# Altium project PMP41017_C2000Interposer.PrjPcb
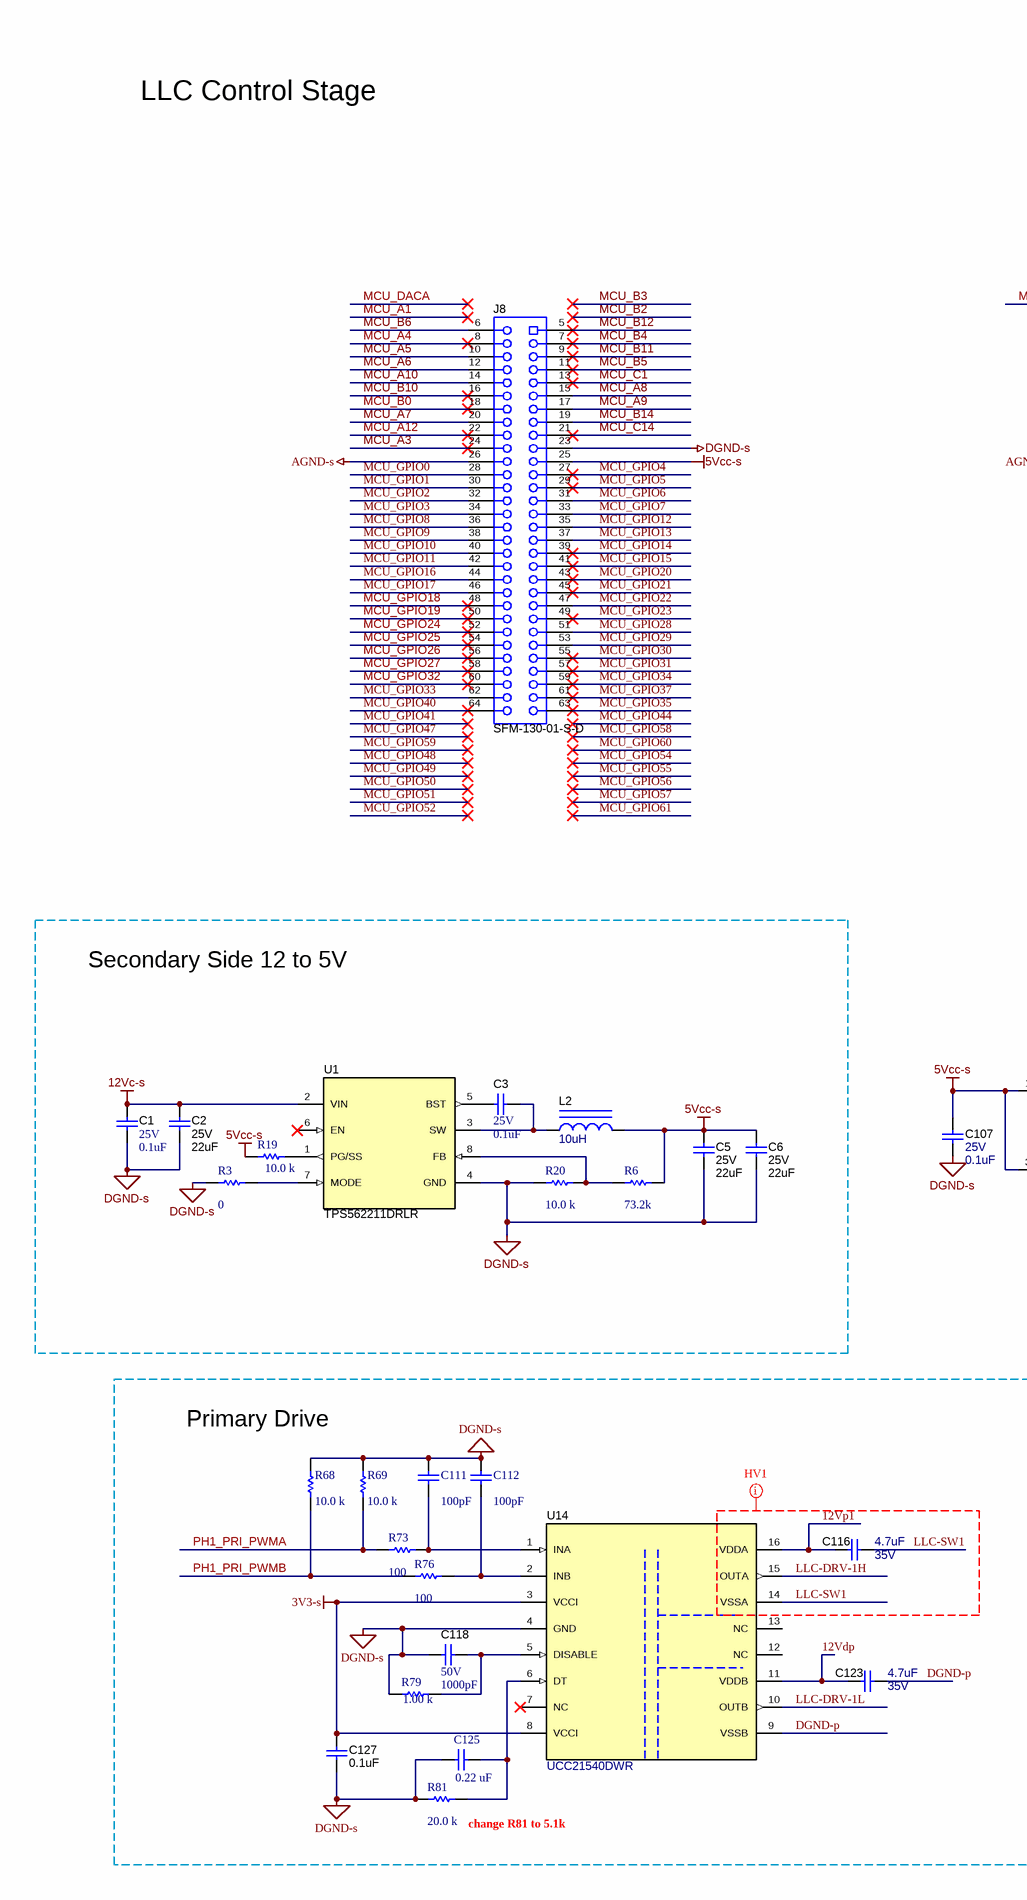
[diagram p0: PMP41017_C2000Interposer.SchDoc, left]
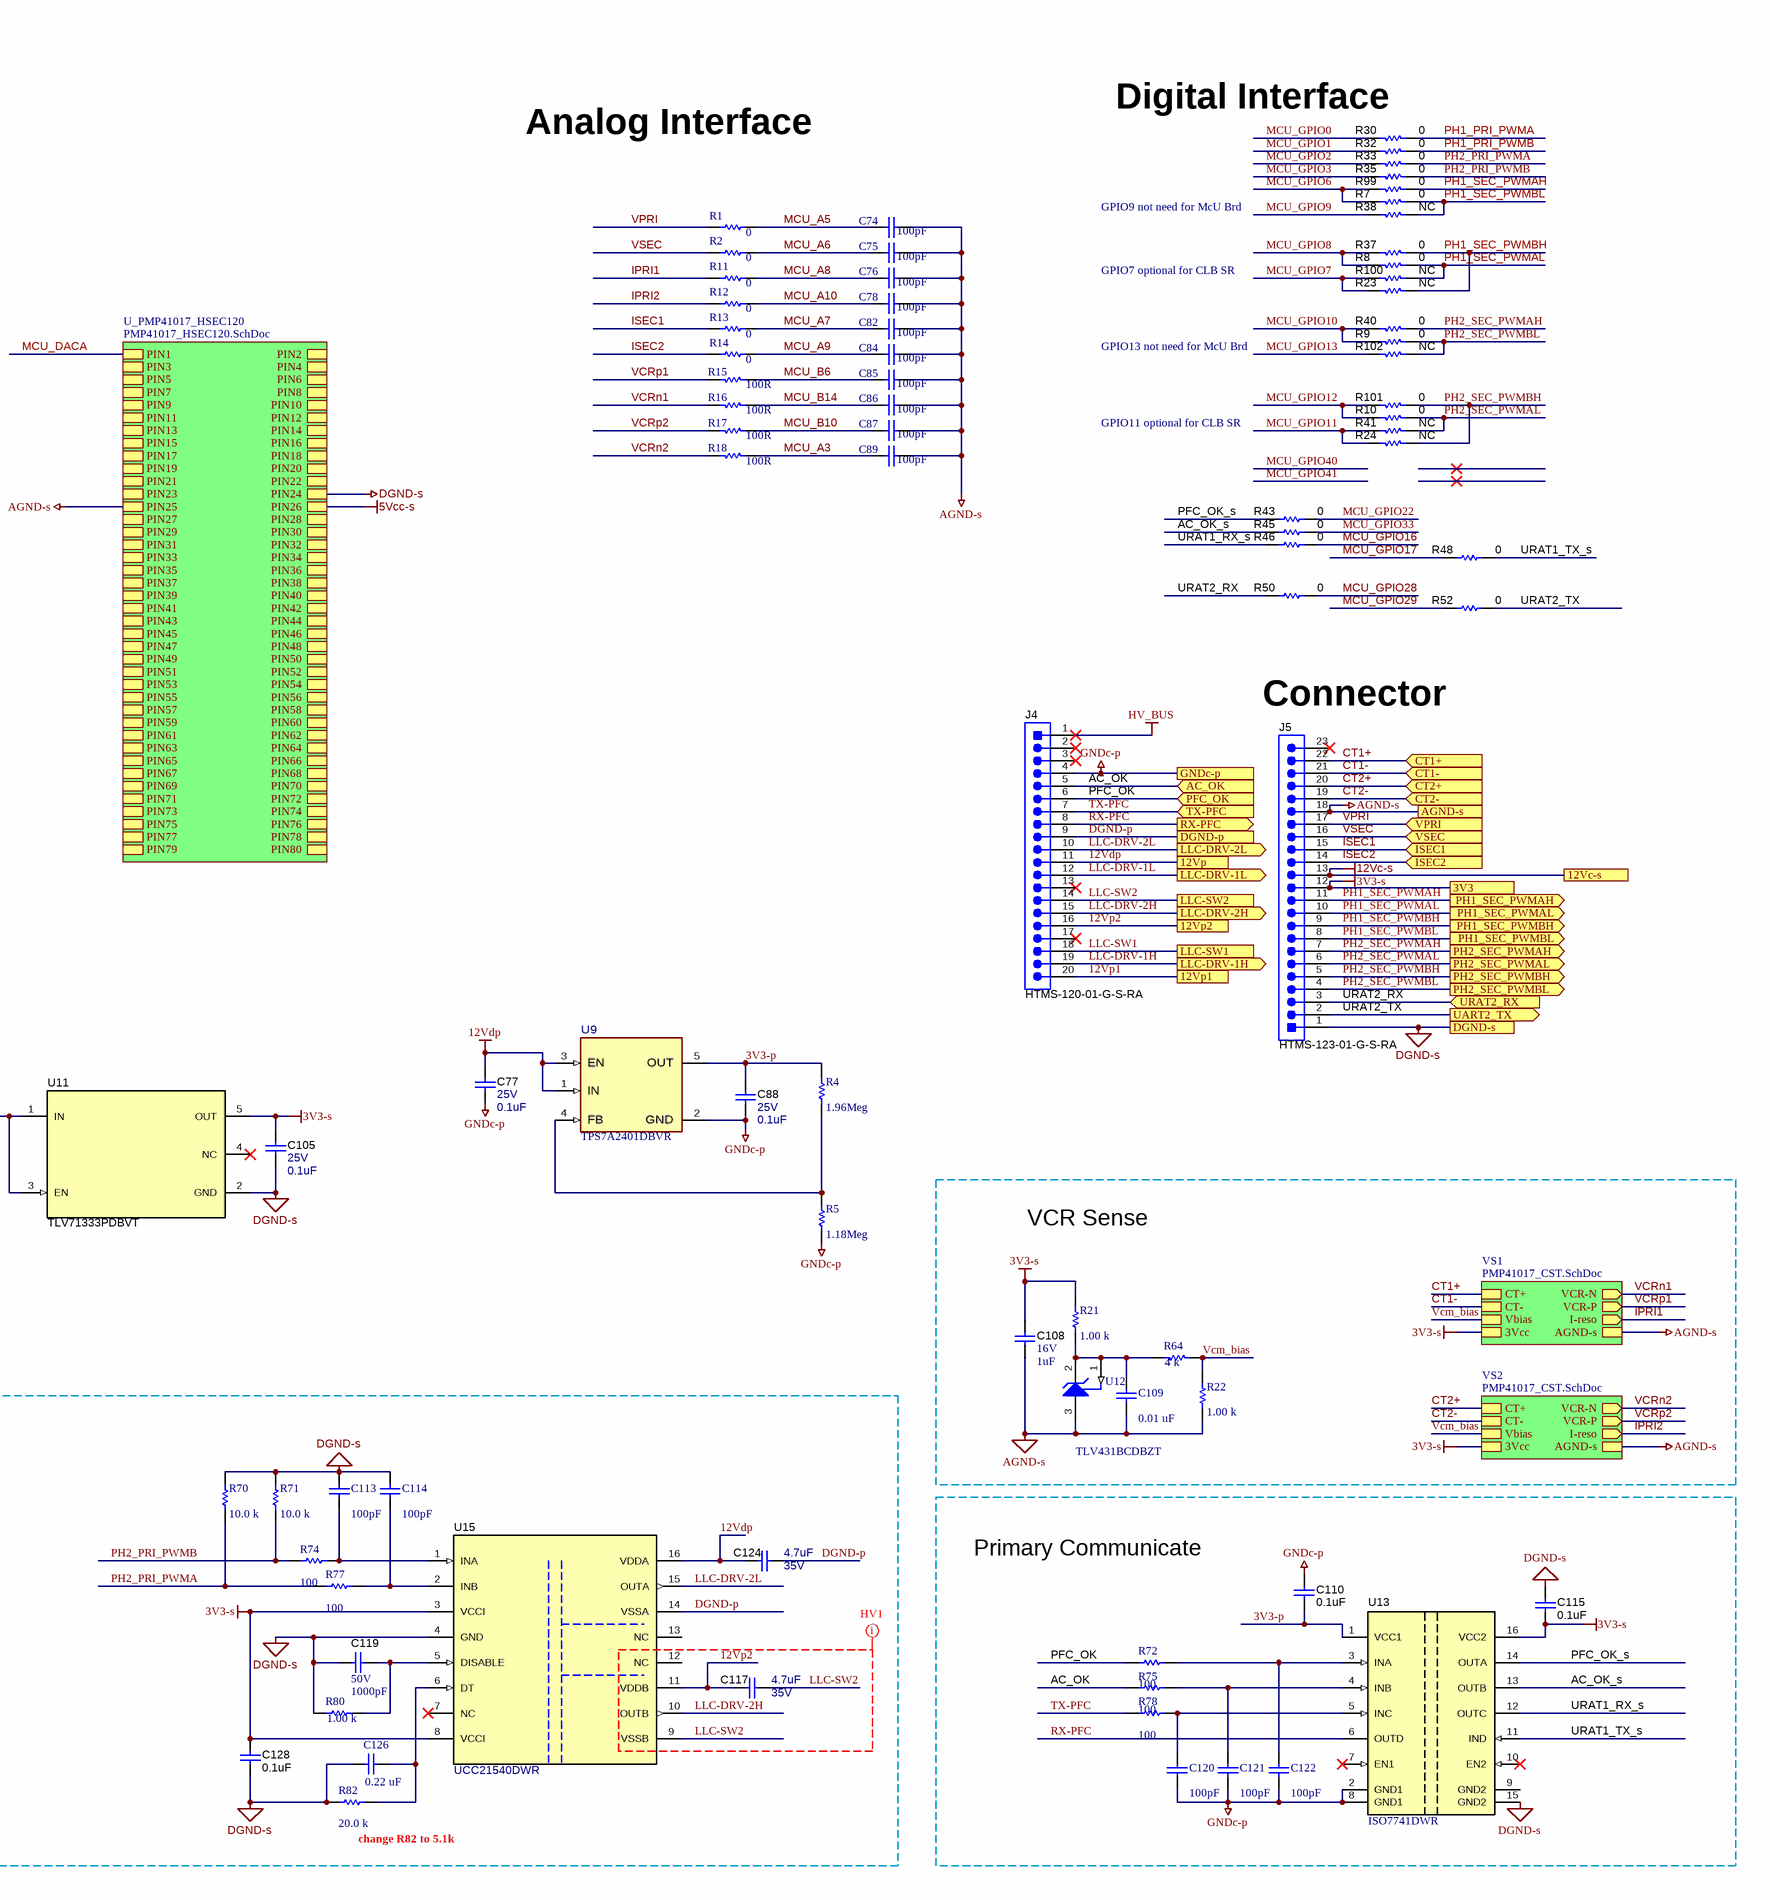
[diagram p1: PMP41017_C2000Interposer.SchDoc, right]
CopyrightYear: 2022; DrawnBy: Desheng Guo; EVM_orderable: Not Orderable; PCB_Layout: Desheng Guo; PCB_Rev: E1; PRJ_Customer: Public Release; PRJ_Engineer: Desheng Guo; PRJ_Number: PMP41017; PRJ_Title: CRPS 12V 3000W LLC C2000 Interposer; SCH_Rev: E1; TechSupport: http://www.ti.com/support; TID: PMP41017
3 sheets, 159 parts. Net scope: hierarchical (ports join the sheet entries above them; power ports are global).
Board file: PMP41017_C2000Interposer.PcbDoc
Sheets:
  PMP41017_C2000Interposer.SchDoc
    VS1 = PMP41017_CST.SchDoc
    VS2 = PMP41017_CST.SchDoc
    U_PMP41017_HSEC120 = PMP41017_HSEC120.SchDoc

## Sheet PMP41017_C2000Interposer.SchDoc: PMP41017 C2000 Interposer
size A2; Date: Not shown in title block; ApprovedBy: Not shown in title block; CheckedBy: Not shown in title block; Author: Not shown in title block; CompanyName: Not shown in title block; DrawnBy1: Desheng Guo; Engineer: Not shown in title block; Organization: Not shown in title block; Address1: Not shown in title block; Address2: Not shown in title block; Address3: Not shown in title block; Address4: Not shown in title block; DocumentNumber: 1; Revision: A; SheetNumber: 1; SheetTotal: 3; PageSetup: Record=PageOptions¦CenterHorizontal=True¦CenterVertical=True¦PrintScale=0.69¦XCorrection=1.00¦YCorrection=1.00¦PrintKind=0¦BorderSize=5000000¦LeftOffset=0¦BottomOffset=0¦Orientation=2¦PaperLength=1000¦PaperWidth=1000¦Scale=100¦PaperSource=15¦PrintQuality=600¦MediaType=1¦DitherType=10¦PaperKind=Letter¦PrintScaleMode=1

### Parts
C1  VDC_V: 25V  ValueDisplayed: 0.1uF  [0402]  (hidden comment: GRM155R71E104KE14D)
C2  VDC_V: 25V  ValueDisplayed: 22uF  [0805_HV]  (hidden comment: GRM21BR61E226ME44L)
C3  VDC_V: 25V  ValueDisplayed: 0.1uF  [0402]  (hidden comment: GRM155R71E104KE14D)
C5  VDC_V: 25V  ValueDisplayed: 22uF  [0805_HV]  (hidden comment: GRM21BR61E226ME44L)
C6  VDC_V: 25V  ValueDisplayed: 22uF  [0805_HV]  (hidden comment: GRM21BR61E226ME44L)
C74  value 100pF  [0402]  (hidden comment: Cap)
C75  value 100pF  [0402]  (hidden comment: Cap)
C76  value 100pF  [0402]  (hidden comment: Cap)
C77  VDC_V: 25V  ValueDisplayed: 0.1uF  [0603]  (hidden comment: C1608X7R1E104K080AA)
C78  value 100pF  [0402]  (hidden comment: Cap)
C82  value 100pF  [0402]  (hidden comment: Cap)
C84  value 100pF  [0402]  (hidden comment: Cap)
C85  value 100pF  [0402]  (hidden comment: Cap)
C86  value 100pF  [0402]  (hidden comment: Cap)
C87  value 100pF  [0402]  (hidden comment: Cap)
C88  VDC_V: 25V  ValueDisplayed: 0.1uF  [0603]  (hidden comment: C1608X7R1E104K080AA)
C89  value 100pF  [0402]  (hidden comment: Cap)
C105  VDC_V: 25V  ValueDisplayed: 0.1uF  [0603]  (hidden comment: C1608X7R1E104K080AA)
C107  VDC_V: 25V  ValueDisplayed: 0.1uF  [0603]  (hidden comment: C1608X7R1E104K080AA)
C108  VDC_V: 16V  ValueDisplayed: 1uF  [0603]  (hidden comment: GCM188R71C105MA64D)
C109  value 0.01 uF  [0402]
C110  ValueDisplayed: 0.1uF  [0402]  (hidden comment: 885012105010)
C111  value 100pF  [0402]  (hidden comment: Cap)
C112  value 100pF  [0402]  (hidden comment: Cap)
C113  value 100pF  [0402]  (hidden comment: Cap)
C114  value 100pF  [0402]  (hidden comment: Cap)
C115  ValueDisplayed: 0.1uF  [0402]  (hidden comment: 885012105010)
C116  VDC_V: 35V  ValueDisplayed: 4.7uF  [0805_HV]  (hidden comment: C2012X7R1V475K125AC)
C117  VDC_V: 35V  ValueDisplayed: 4.7uF  [0805_HV]  (hidden comment: C2012X7R1V475K125AC)
C118  VDC_V: 50V  ValueDisplayed: 1000pF  [0402]  (hidden comment: GRM155R71H102KA01D)
C119  VDC_V: 50V  ValueDisplayed: 1000pF  [0402]  (hidden comment: GRM155R71H102KA01D)
C120  value 100pF  [0402]  (hidden comment: Cap)
C121  value 100pF  [0402]  (hidden comment: Cap)
C122  value 100pF  [0402]  (hidden comment: Cap)
C123  VDC_V: 35V  ValueDisplayed: 4.7uF  [0805_HV]  (hidden comment: C2012X7R1V475K125AC)
C124  VDC_V: 35V  ValueDisplayed: 4.7uF  [0805_HV]  (hidden comment: C2012X7R1V475K125AC)
C125  value 0.22 uF  [0402]
C126  value 0.22 uF  [0402]
C127  ValueDisplayed: 0.1uF  [0402]  (hidden comment: 885012105010)
C128  ValueDisplayed: 0.1uF  [0402]  (hidden comment: 885012105010)
J4  HTMS-120-01-G-S-RA  [HTMS-120-01-G-S-RA]
J5  HTMS-123-01-G-S-RA  [HTMS-123-01-G-S-RA]
J8  SFM-130-01-S-D  [Samtec_SFM-130-01-x-D]
L2  ValueDisplayed: 10uH  [VLS252010HBX]  (hidden comment: 74438323100)
R1  value 0  [0402]
R2  value 0  [0402]
R3  value 0  [0402]
R4  value 1.96Meg  [0402]
R5  value 1.18Meg  [0402]
R6  73.2k  [0402]
R7  ValueDisplayed: 0  [0402]  (hidden comment: CRCW04020000Z0ED)
R8  ValueDisplayed: 0  [0402]  (hidden comment: CRCW04020000Z0ED)
R9  ValueDisplayed: 0  [0402]  (hidden comment: CRCW04020000Z0ED)
R10  ValueDisplayed: 0  [0402]  (hidden comment: CRCW04020000Z0ED)
R11  value 0  [0402]
R12  value 0  [0402]
R13  value 0  [0402]
R14  value 0  [0402]
R15  value 100R  [0402]
R16  value 100R  [0402]
R17  100R  [0402]
R18  value 100R  [0402]
R19  value 10.0 k  [0402]
R20  value 10.0 k  [0402]
R21  value 1.00 k  [0402]
R22  value 1.00 k  [0402]
R23  ValueDisplayed: NC  [0402]  (hidden comment: CRCW04020000Z0ED)  (no BOM)
R24  ValueDisplayed: NC  [0402]  (hidden comment: CRCW04020000Z0ED)  (no BOM)
R30  ValueDisplayed: 0  [0402]  (hidden comment: CRCW04020000Z0ED)
R32  ValueDisplayed: 0  [0402]  (hidden comment: CRCW04020000Z0ED)
R33  ValueDisplayed: 0  [0402]  (hidden comment: CRCW04020000Z0ED)
R35  ValueDisplayed: 0  [0402]  (hidden comment: CRCW04020000Z0ED)
R37  ValueDisplayed: 0  [0402]  (hidden comment: CRCW04020000Z0ED)
R38  ValueDisplayed: NC  [0402]  (hidden comment: CRCW04020000Z0ED)  (no BOM)
R40  ValueDisplayed: 0  [0402]  (hidden comment: CRCW04020000Z0ED)
R41  ValueDisplayed: NC  [0402]  (hidden comment: CRCW04020000Z0ED)  (no BOM)
R43  ValueDisplayed: 0  [0402]  (hidden comment: CRCW04020000Z0ED)
R45  ValueDisplayed: 0  [0402]  (hidden comment: CRCW04020000Z0ED)
R46  ValueDisplayed: 0  [0402]  (hidden comment: CRCW04020000Z0ED)
R48  ValueDisplayed: 0  [0402]  (hidden comment: CRCW04020000Z0ED)
R50  ValueDisplayed: 0  [0402]  (hidden comment: CRCW04020000Z0ED)
R52  ValueDisplayed: 0  [0402]  (hidden comment: CRCW04020000Z0ED)
R64  value 4 k  [0402]
R68  value 10.0 k  [0402]
R69  value 10.0 k  [0402]
R70  value 10.0 k  [0402]
R71  value 10.0 k  [0402]
R72  value 100  [0402]
R73  value 100  [0402]
R74  value 100  [0402]
R75  value 100  [0402]
R76  value 100  [0402]
R77  value 100  [0402]
R78  value 100  [0402]
R79  value 1.00 k  [0402]
R80  value 1.00 k  [0402]
R81  value 20.0 k  [0402]
R82  value 20.0 k  [0402]
R99  ValueDisplayed: 0  [0402]  (hidden comment: CRCW04020000Z0ED)
R100  ValueDisplayed: NC  [0402]  (hidden comment: CRCW04020000Z0ED)  (no BOM)
R101  ValueDisplayed: 0  [0402]  (hidden comment: CRCW04020000Z0ED)
R102  ValueDisplayed: NC  [0402]  (hidden comment: CRCW04020000Z0ED)  (no BOM)
U1  TPS562211DRLR  [DRL0008A]
U9  TPS7A2401DBVR  [DBV0005A-MFG]
U11  TLV71333PDBVT  [DBV0005A_N]
U12  TLV431BCDBZT  [DBZ0003A_N]
U13  ISO7741DWR  [DW0016B_HV]
U14  UCC21540DWR  [DW0016B_HV]
U15  UCC21540DWR  [DW0016B_HV]

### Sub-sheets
U_PMP41017_HSEC120 = PMP41017_HSEC120.SchDoc: PIN1, PIN3, PIN5, PIN7, PIN9, PIN11, PIN13, PIN15, PIN17, PIN19, PIN21, PIN23, PIN25, PIN27, PIN29, PIN31, PIN33, PIN35, PIN37, PIN39, PIN41, PIN43, PIN45, PIN47, PIN49, PIN51, PIN53, PIN55, PIN57, PIN59, PIN61, PIN63, PIN65, PIN67, PIN69, PIN71, PIN73, PIN75, PIN77, PIN79, PIN2, PIN4, PIN6, PIN8, PIN10, PIN12, PIN14, PIN16, PIN18, PIN20, PIN22, PIN24, PIN26, PIN28, PIN30, PIN32, PIN34, PIN36, PIN38, PIN40, PIN42, PIN44, PIN46, PIN48, PIN50, PIN52, PIN54, PIN56, PIN58, PIN60, PIN62, PIN64, PIN66, PIN68, PIN70, PIN72, PIN74, PIN76, PIN78, PIN80
VS1 = PMP41017_CST.SchDoc: CT+, CT-, Vbias, AGND-s, VCR-N (out), VCR-P (out), I-reso (out), 3Vcc
VS2 = PMP41017_CST.SchDoc: CT+, CT-, Vbias, AGND-s, VCR-N (out), VCR-P (out), I-reso (out), 3Vcc

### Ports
3V3, 12Vc-s, 12Vp, 12Vp1, 12Vp2, AC_OK (in), AGND-s, CT1+ (in), CT1- (in), CT2+ (in), CT2- (in), DGND-p, DGND-s, GNDc-p, ISEC1 (in), ISEC2 (in), LLC-DRV-1H (out), LLC-DRV-1L (out), LLC-DRV-2H (out), LLC-DRV-2L (out), LLC-SW1, LLC-SW2, PFC_OK (in), PH1_SEC_PWMAH (out), PH1_SEC_PWMAL (out), PH1_SEC_PWMBH (out), PH1_SEC_PWMBL (out), PH2_SEC_PWMAH (out), PH2_SEC_PWMAL (out), PH2_SEC_PWMBH (out), PH2_SEC_PWMBL (out), RX-PFC (out), TX-PFC (in), UART2_TX (out), URAT2_RX (in), VPRI (in), VSEC (in)

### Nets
3V3-s: C105.1 C108.1 C115.1 C127.1 C128.1 J5.12 R21.2 U11.5(OUT) U13.16(VCC2) U14.3(VCCI) U14.8(VCCI) U15.3(VCCI) U15.8(VCCI) ; port 3V3, sheet VS1/3Vcc, sheet VS2/3Vcc
5Vcc-s: C5.1 C6.1 C107.1 J8.25 L2.2 R6.2 R19.2 U11.1(IN) U11.3(EN) ; sheet U_PMP41017_HSEC120/PIN26
12Vc-s: C1.2 C2.1 J5.13 U1.2(VIN) ; port 12Vc-s
12Vdp: C77.1 C123.1 C124.1 J4.11 U9.1(IN) U9.3(EN) U14.11(VDDB) U15.16(VDDA) ; port 12Vp
AGND-s: C74.1 C75.1 C76.1 C78.1 C82.1 C84.1 C85.1 C86.1 C87.1 C89.1 C108.2 C109.1 J5.18 J8.26 R22.1 U12.3(ANODE) ; port AGND-s, sheet VS1/AGND-s, sheet VS2/AGND-s, sheet U_PMP41017_HSEC120/PIN25
CT1+: J5.20 J5.22 ; port CT1+, port CT2+, sheet VS1/CT+, sheet VS2/CT+  [also labelled CT2+]
CT1-: J5.19 J5.21 ; port CT1-, port CT2-, sheet VS1/CT-, sheet VS2/CT-  [also labelled CT2-]
DGND-s: C1.1 C2.2 C5.2 C6.2 C105.2 C107.2 C111.2 C112.2 C113.2 C114.2 C115.2 C118.2 C119.2 C125.1 C126.1 C127.2 C128.2 J5.1 J8.23 R3.1 R20.2 R68.2 R69.2 R70.2 R71.2 R79.1 R80.1 R81.1 R82.1 U1.4(GND) U11.2(GND) U13.15(GND2) U14.4(GND) U15.4(GND) ; port DGND-s, sheet U_PMP41017_HSEC120/PIN24
GNDc-p: C77.2 C88.2 C110.2 C120.1 C121.1 C122.1 J4.4 R5.1 U9.2(GND) U13.2(GND1) U13.8(GND1) ; port GNDc-p
HV_BUS: J4.1
Vcm_bias: R22.2 R64.2 ; sheet VS1/Vbias, sheet VS2/Vbias
3V3-p: C88.1 C110.1 R4.2 U9.5(OUT) U13.1(VCC1)  [project net 3V3-p_1]
12Vp1: C116.1 J4.20 U14.16(VDDA) ; port 12Vp1
12Vp2: C117.1 J4.16 U15.11(VDDB) ; port 12Vp2
AC_OK: J4.5 R75.1 ; port AC_OK
AC_OK_s: R45.1 U13.13(OUTB)  [project net AC_OK_s_1]
DGND-p: C123.2 C124.2 J4.9 U14.9(VSSB) U15.14(VSSA) ; port DGND-p
IPRI1: R11.2 ; sheet VS1/I-reso  [project net I-reso]
IPRI2: R12.2 ; sheet VS2/I-reso  [project net I-reso]
ISEC1: J5.15 R13.2 ; port ISEC1
ISEC2: J5.14 R14.2 ; port ISEC2
LLC-DRV-1H: J4.19 U14.15(OUTA) ; port LLC-DRV-1H
LLC-DRV-1L: J4.12 U14.10(OUTB) ; port LLC-DRV-1L
LLC-DRV-2H: J4.15 U15.10(OUTB) ; port LLC-DRV-2H
LLC-DRV-2L: J4.10 U15.15(OUTA) ; port LLC-DRV-2L
LLC-SW1: C116.2 J4.18 U14.14(VSSA) ; port LLC-SW1
LLC-SW2: C117.2 J4.14 U15.9(VSSB) ; port LLC-SW2
MCU_A3: C89.2 J8.24 R18.1  [project net MCU_A3_1]
MCU_A4: J8.8  [project net MCU_A4_1]
MCU_A5: C74.2 J8.10 R1.1  [project net MCU_A5_1]
MCU_A6: C75.2 J8.12 R2.1  [project net MCU_A6_1]
MCU_A7: C82.2 J8.20 R13.1  [project net MCU_A7_1]
MCU_A8: C76.2 J8.15 R11.1  [project net MCU_A8_1]
MCU_A9: C84.2 J8.17 R14.1  [project net MCU_A9_1]
MCU_A10: C78.2 J8.14 R12.1  [project net MCU_A10_1]
MCU_A12: J8.22  [project net MCU_A12_1]
MCU_B0: J8.18  [project net MCU_B0_1]
MCU_B4: J8.7  [project net MCU_B4_1]
MCU_B5: J8.11  [project net MCU_B5_1]
MCU_B6: C85.2 J8.6 R15.1  [project net MCU_B6_1]
MCU_B10: C87.2 J8.16 R17.1  [project net MCU_B10_1]
MCU_B11: J8.9  [project net MCU_B11_1]
MCU_B12: J8.5  [project net MCU_B12_1]
MCU_B14: C86.2 J8.19 R16.1  [project net MCU_B14_1]
MCU_C1: J8.13  [project net MCU_C1_1]
MCU_C14: J8.21  [project net MCU_C14_1]
MCU_GPIO0: J8.28 R30.2  [project net MCU_GPIO0_1]
MCU_GPIO1: J8.30 R32.2  [project net MCU_GPIO1_1]
MCU_GPIO2: J8.32 R33.2  [project net MCU_GPIO2_1]
MCU_GPIO3: J8.34 R35.2  [project net MCU_GPIO3_1]
MCU_GPIO4: J8.27  [project net MCU_GPIO4_1]
MCU_GPIO5: J8.29  [project net MCU_GPIO5_1]
MCU_GPIO6: J8.31 R7.2 R99.2  [project net MCU_GPIO6_1]
MCU_GPIO7: J8.33 R23.2 R100.2  [project net MCU_GPIO7_1]
MCU_GPIO8: J8.36 R8.2 R37.2  [project net MCU_GPIO8_1]
MCU_GPIO9: J8.38 R38.2  [project net MCU_GPIO9_1]
MCU_GPIO10: J8.40 R9.2 R40.2  [project net MCU_GPIO10_1]
MCU_GPIO11: J8.42 R24.2 R41.2  [project net MCU_GPIO11_1]
MCU_GPIO12: J8.35 R10.2 R101.2  [project net MCU_GPIO12_1]
MCU_GPIO13: J8.37 R102.2  [project net MCU_GPIO13_1]
MCU_GPIO14: J8.39  [project net MCU_GPIO14_1]
MCU_GPIO15: J8.41  [project net MCU_GPIO15_1]
MCU_GPIO16: J8.44 R46.2  [project net MCU_GPIO16_1]
MCU_GPIO17: J8.46 R48.1  [project net MCU_GPIO17_1]
MCU_GPIO18: J8.48  [project net MCU_GPIO18_1]
MCU_GPIO19: J8.50  [project net MCU_GPIO19_1]
MCU_GPIO20: J8.43  [project net MCU_GPIO20_1]
MCU_GPIO21: J8.45  [project net MCU_GPIO21_1]
MCU_GPIO22: J8.47 R43.2  [project net MCU_GPIO22_1]
MCU_GPIO23: J8.49  [project net MCU_GPIO23_1]
MCU_GPIO24: J8.52  [project net MCU_GPIO24_1]
MCU_GPIO25: J8.54  [project net MCU_GPIO25_1]
MCU_GPIO26: J8.56  [project net MCU_GPIO26_1]
MCU_GPIO27: J8.58  [project net MCU_GPIO27_1]
MCU_GPIO28: J8.51 R50.2  [project net MCU_GPIO28_1]
MCU_GPIO29: J8.53 R52.1  [project net MCU_GPIO29_1]
MCU_GPIO30: J8.55  [project net MCU_GPIO30_1]
MCU_GPIO31: J8.57  [project net MCU_GPIO31_1]
MCU_GPIO32: J8.60  [project net MCU_GPIO32_1]
MCU_GPIO33: J8.62 R45.2  [project net MCU_GPIO33_1]
MCU_GPIO34: J8.59  [project net MCU_GPIO34_1]
MCU_GPIO35: J8.63  [project net MCU_GPIO35_1]
MCU_GPIO37: J8.61  [project net MCU_GPIO37_1]
MCU_GPIO40: J8.64  [project net MCU_GPIO40_1]
PFC_OK: J4.6 R72.1 ; port PFC_OK
PFC_OK_s: R43.1 U13.14(OUTA)  [project net PFC_OK_s_1]
PH1_PRI_PWMA: R30.1 R69.1 R73.1  [project net PH1_PRI_PWMA_1]
PH1_PRI_PWMB: R32.1 R68.1 R76.1  [project net PH1_PRI_PWMB_1]
PH1_SEC_PWMAH: J5.11 R99.1 ; port PH1_SEC_PWMAH
PH1_SEC_PWMAL: J5.10 R8.1 R100.1 ; port PH1_SEC_PWMAL
PH1_SEC_PWMBH: J5.9 R23.1 R37.1 ; port PH1_SEC_PWMBH
PH1_SEC_PWMBL: J5.8 R7.1 R38.1 ; port PH1_SEC_PWMBL
PH2_PRI_PWMA: R33.1 R70.1 R77.1  [project net PH2_PRI_PWMA_1]
PH2_PRI_PWMB: R35.1 R71.1 R74.1  [project net PH2_PRI_PWMB_1]
PH2_SEC_PWMAH: J5.7 R40.1 ; port PH2_SEC_PWMAH
PH2_SEC_PWMAL: J5.6 R10.1 R41.1 ; port PH2_SEC_PWMAL
PH2_SEC_PWMBH: J5.5 R24.1 R101.1 ; port PH2_SEC_PWMBH
PH2_SEC_PWMBL: J5.4 R9.1 R102.1 ; port PH2_SEC_PWMBL
RX-PFC: J4.8 U13.6(OUTD) ; port RX-PFC
TX-PFC: J4.7 R78.1 ; port TX-PFC
URAT1_RX_s: R46.1 U13.12(OUTC)  [project net URAT1_RX_s_1]
URAT1_TX_s: R48.2 U13.11(IND)  [project net URAT1_TX_s_1]
URAT2_RX: J5.3 R50.1 ; port URAT2_RX
URAT2_TX: J5.2 R52.2 ; port UART2_TX
VCRn1: R16.2 ; sheet VS1/VCR-N  [project net VCR-N]
VCRn2: R18.2 ; sheet VS2/VCR-N  [project net VCR-N]
VCRp1: R15.2 ; sheet VS1/VCR-P  [project net VCR-P]
VCRp2: R17.2 ; sheet VS2/VCR-P  [project net VCR-P]
VPRI: J5.17 R1.2 ; port VPRI
VSEC: J5.16 R2.2 ; port VSEC
NetC3_1: C3.1 U1.5(BST)
NetC3_2: C3.2 L2.1 U1.3(SW)
NetC109_2: C109.2 R21.1 R64.1 U12.1(REF) U12.2(CATHODE)
NetC111_1: C111.1 R73.2 U14.1(INA)
NetC112_1: C112.1 R76.2 U14.2(INB)
NetC113_1: C113.1 R74.2 U15.1(INA)
NetC114_1: C114.1 R77.2 U15.2(INB)
NetC118_1: C118.1 R79.2 U14.5(DISABLE)
NetC119_1: C119.1 R80.2 U15.5(DISABLE)
NetC120_2: C120.2 R78.2 U13.5(INC)
NetC121_2: C121.2 R75.2 U13.4(INB)
NetC122_2: C122.2 R72.2 U13.3(INA)
NetC125_2: C125.2 R81.2 U14.6(DT)
NetC126_2: C126.2 R82.2 U15.6(DT)
NetR3_2: R3.2 U1.7(MODE)
NetR4_1: R4.1 R5.2 U9.4(FB)
NetR6_1: R6.1 R20.1 U1.8(FB)
NetR19_1: R19.1 U1.1(PG/SS)

Not connected (* = marked no-connect by the designer): J4 2* 3* 13* 17*; J5 23*; U1 6(EN)*; U11 4(NC)*; U13 7(EN1)* 9(GND2) 10(EN2)*; U14 7(NC)* 12(NC) 13(NC); U15 7(NC)* 12(NC) 13(NC)

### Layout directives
net class HV: 12Vp1, 12Vp2, LLC-DRV-1H, LLC-DRV-2H, LLC-SW1, LLC-SW2

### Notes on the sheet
- Analog Interface
- Digital Interface
- LLC Control Stage
- GPIO9 not need for McU Brd
- GPIO7 optional for CLB SR
- GPIO13 not need for McU Brd
- GPIO11 optional for CLB SR
- (near J5) Connector
- Secondary Side 12 to 5V
- VCR Sense
- Primary Drive
- Primary Communicate
- (near R81) change R81 to 5.1k
- (near R82) change R82 to 5.1k

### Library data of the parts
C1 C3 = CMP-0006659-2: CAP, CERM, 0.1 uF, 25 V, +/- 10%, X7R, 0402; Manufacturer: MuRata; TaMin_C: -55°C; Polarized: N; SizeAreaWB_mm2: 3; Value1: Unknown; U/M: EA; Value: 0.1uF; TaMax_C: 125°C; SizeZ_mm: 0.6; SizeX_mm: 1; SizeY_mm: 0.5; Cap_F: 100nF; AEC Category: Q200
C2 C5 C6 = CMP-0008305-2: CAP, CERM, 22 uF, 25 V, +/- 20%, X5R, 0805; Manufacturer: MuRata; TaMin_C: -55°C; Polarized: N; SizeAreaWB_mm2: 6.75; Value1: Unknown; U/M: EA; Value: 22uF; TaMax_C: 85°C; SizeZ_mm: 1.45; SizeX_mm: 2; SizeY_mm: 1.25; Cap_Case: 0805; SizeArea_mm2: 2.5; Cap_F: 22µF; AEC Category: Q200
C74-C76 C78 C82 C84-C87 C89 C111-C114 C120-C122 = Cap: CAP, CERM, 100 pF, 25 V, +/- 10%, X7R,0402
C77 C88 C105 C107 = CMP-0007039-5: CAP, CERM, 0.1 uF, 25 V, +/- 10%, X7R, 0603; Manufacturer: TDK; TaMin_C: -55°C; Polarized: N; SizeAreaWB_mm2: 4.68; Value1: Unknown; U/M: EA; Value: 0.1uF; TaMax_C: 125°C; SizeZ_mm: 1; SizeX_mm: 1.6; SizeY_mm: 0.8; SizeArea_mm2: 1.28; Cap_F: 100nF; AEC Category: Q200
C108 = CMP-0007137-5: CAP, CERM, 1 uF, 16 V, +/- 20%, X7R, AEC-Q200 Grade 1, 0603; Manufacturer: MuRata; TaMin_C: -55°C; Polarized: N; SizeAreaWB_mm2: 4.68; Value1: Unknown; U/M: EA; Value: 1uF; TaMax_C: 125°C; SizeZ_mm: 1; SizeX_mm: 1.6; SizeY_mm: 0.8; SizeArea_mm2: 1.28; CompType: Capacitor; AEC Qualified: Y; Cap_F: 1µF; AEC Category: Q200
C109 = Cap: CAP, CERM, 0.01 uF, 50 V, +/- 10%, X7R, 0402
C110 C115 = CMP-0006221-2: CAP, CERM, 0.1 uF, 10 V, +/- 20%, X5R, 0402; Manufacturer: Wurth Elektronik; Polarized: N; CompType: Capacitor; Value: 0.1uF; U/M: EA; Cap_F: 100nF; Value1: Unknown; VDC_V: 10V; TaMin_C: -55°C; TaMax_C: 85°C; SizeArea_mm2: 0.5; SizeAreaWB_mm2: 3; SizeX_mm: 1; SizeZ_mm: 0.6; AEC Category: Q200
C116 C117 C123 C124 = CMP-0007885-2: CAP, CERM, 4.7 uF, 35 V, +/- 10%, X7R, 0805; Manufacturer: TDK; TaMin_C: -55°C; ESR_ohm: 2.346m; Polarized: N; SizeAreaWB_mm2: 6.75; Value1: 0.002346 ohm; U/M: EA; Value: 4.7uF; TaMax_C: 125°C; SizeZ_mm: 1.45; SizeX_mm: 2; SizeY_mm: 1.25; Cap_Case: 0805; SizeArea_mm2: 2.5; Cap_F: 4.7µF; IRMS_A: 4.26021A; AEC Category: Q200
C118 C119 = CMP-0006673-2: CAP, CERM, 1000 pF, 50 V, +/- 10%, X7R, 0402; Manufacturer: MuRata; TaMin_C: -55°C; Polarized: N; SizeAreaWB_mm2: 3; Value1: Unknown; U/M: EA; Value: 1000pF; TaMax_C: 125°C; SizeZ_mm: 0.6; SizeX_mm: 1; SizeY_mm: 0.5; Cap_F: 1nF; AEC Category: Q200
C125 C126 = Cap: CAP, CERM, 0.22 uF, 50 V, +/- 10%, X7R, 0402
C127 C128 = CMP-0006221-2: CAP, CERM, 0.1 uF, 10 V, +/- 20%, X5R, 0402; Manufacturer: Wurth Elektronik; Polarized: N; CompType: Capacitor; Value: 0.1uF; U/M: EA; Cap_F: 100nF; Value1: Unknown; VDC_V: 10V; TaMin_C: -55°C; TaMax_C: 85°C; AEC Category: Q200; SizeArea_mm2: 0.5; SizeAreaWB_mm2: 3; SizeX_mm: 1; SizeZ_mm: 0.6
J4 = Header_20x1: Header, 1.27mm, 20x1, Gold with Tin tail, TH, Right Angle; Manufacturer: Samtec; Pitch_mm: 1.27; Gender: Male; Row_Count: 1; Current_A: 1A; Cert_UL: Y; Shrouded: N
J5 = Header_23x1: Header, 1.27mm, 23x1, Gold with Tin tail, TH, Right Angle; Manufacturer: Samtec; Pitch_mm: 1.27; Gender: Male; Row_Count: 1; Current_A: 1A; Cert_UL: Y; Shrouded: N
J8 = Receptacle_30x2: Receptacle, 1.27mm, 30x2, Gold, TH; Manufacturer: Samtec; Pitch_mm: 1.27; Gender: Female; Cert_CSA: Y; Current_A: 3.2A; Voltage_V: 250V; CT: True; Row_Count: 2; CompType: Socket Strip; CNHeader: False
L2 = CMP-0063086-1: Inductor, Wirewound, Ferrite, 10 uH, 0.68 A, 0.46 ohm, SMD; Manufacturer: Würth Elektronik; Isat: 1.35A @ 20% inductance drop; Irms: 0.60A @ 40C rise; Green_Lifecycle: Active; SizeAreaWB_mm2: 10.5; DCR_ohm: 0.46; Green_REACh: Passed; Value1: 0.843 ohm; Value: 10uH; Imax_A: 600mA; SizeZ_mm: 1; SizeX_mm: 2.5; SizeY_mm: 2; Value2: 0.6A; SizeArea_mm2: 5; Ind_H: 10µH; AEC Qualified: N; AEC Category: Q200
R1 R2 R11-R14 = Res1: RES, 0, 5%, 0.063 W, AEC-Q200 Grade 0, 0402
R3 = Res1: RES, 0, 5%, 0.1 W, AEC-Q200 Grade 0, 0402
R4 = Res1: RES, 1.96Meg, 1%, 0.1 W, 0402
R5 = Res1: RES, 1.18Meg, 1%, 0.1 W, 0402
R6 = Res1: RES, 73.2 k, 1%, 0.1 W, AEC-Q200 Grade 0, 0402
R7-R10 R23 R24 R30 R32 R33 R35 R37 R38 R40 R41 R43 R45 R46 R48 R50 R52 R99-R102 = CMP-0026822-3: RES, 0, 5%, 0.063 W, AEC-Q200 Grade 0, 0402; Manufacturer: Vishay-Dale; CompType: Resistor; Value: 0; Value_Code: 0000; Power_W: 63mW; Value2: 0.063W; VDC_V: 50V; TempCo: 200 ppm/C; SizeArea_mm2: 0.5; SizeX_mm: 1; SizeZ_mm: 0.6; EIA_Code: E24; AEC Category: Q200; AEC Qualified: Y
R15-R18 = Res1: RES, 100R, 1%, 0402
R19 R20 R68-R71 = Res1: RES, 10.0 k, 1%, 0.1 W, 0402
R21 R22 R79 R80 = Res1: RES, 1.00 k, 1%, 0402
R64 = Res1: RES, 4 k, 1%,0402
R72-R78 = Res1: RES, 100, 1%, 0402
R81 R82 = Res1: RES, 20.0 k, 1%, 0402
U1 = CMP-0861057-2: 4.2-V to 17-V Input, 2-A Synchronous Buck Converter, DRL0008A (SOT-5X3-8); Alternate Manufacturer: Texas Instruments; AEC Category: Q200; SizeX_mm: 1.6; SizeY_mm: 2.1; CompType: IC; SizeZ_mm: 0.6; SizeAreaWB_mm2: 8.06; AEC Qualified: N; SizeArea_mm2: 3.36
U9 = CMP-0089843-1: Linear Voltage Regulator IC 1 Output 200mA SOT-23-5; Manufacturer: Texas Instruments; Output Type: AdjustableProgrammable; Accuracy Percentage: 2%; AEC Qualified: No; Max Supply Voltage: 18V; Dropout Voltage: 160mV; SizeZ_mm: 1.45mm; Output Voltage: 1.24-17.75V; Min Supply Voltage: 2.4V; TJmax_C: +125°C; Nominal Supply Current: 2uA; Number Of Outputs: 1; Standoff Height: 0mm
U11 = TLV71333PQDBVRQ1: Capacitor-Free, 150-mA, Low-Dropout Regulator with Foldback Current Limit for Portable Devices, DBV0005A; Manufacturer: Texas Instruments; SymbolCreator: Altium; SizeArea_mm2: 8.12; SizeAreaWB_mm2: 14.82; SizeX_mm: 2.8; SizeY_mm: 2.9; SizeZ_mm: 1.45; CompType: IC; U/M: EA
U12 = CMP-0033068-1: Low-Voltage Adjustable Precision Shunt Regulator, 15 mA, 0 to 70 degC, 3-pin SOT-23 (DBZ), Green (RoHS & no Sb/Br); Manufacturer: Texas Instruments; Temp Coeff(Max)(ppm/ degree C): 129; VO Adj(Max)(V): 6; VO Adj(Min)(V): 1.24; Rating: Catalog; SubFamily: Shunt Voltage Reference; Initial Accuracy @ 25/deg C(%): 0.5; Iout/Iz(Max)(mA): 15; Min Iz for Regulation(uA): 80
U13 = CMP-0076064-3: High-Speed, Low-Power, Robust EMC Quad-Channel Digital Isolator, DW0016B (SOIC-16); Manufacturer: Texas Instruments; Green_Lifecycle: Active; AEC Category: Q200; CompType: IC; Green_REACh: Passed; SizeAreaWB_mm2: 152.52; SizeX_mm: 10.4; Rating: Catalog; SizeY_mm: 10.3; AEC Qualified: N; SizeZ_mm: 2.65; SizeArea_mm2: 107.12
U14 U15 = CMP-0073643-4: 4A/6A, 5.7 kVrms Isolated Dual Channel Gate Driver, DW0016B (SOIC-16); Alternate Manufacturer: Texas Instruments; CompType: IC; SizeArea_mm2: 107.12; SizeY_mm: 10.3; Rating: Catalog; AEC Category: Q200; SizeZ_mm: 2.65; SizeX_mm: 10.4; AEC Qualified: N; SizeAreaWB_mm2: 152.52

## Sheet PMP41017_CST.SchDoc
size A3; Date: Not shown in title block; ApprovedBy: Not shown in title block; CheckedBy: Not shown in title block; Author: Not shown in title block; CompanyName: Not shown in title block; DrawnBy: Desheng Guo; Engineer: Not shown in title block; Organization: Not shown in title block; Address1: Not shown in title block; Address2: Not shown in title block; Address3: Not shown in title block; Address4: Not shown in title block; DocumentNumber: 1; Revision: Use project parameter SCH_Rev; SheetNumber: 6; SheetTotal: 7; PageSetup: Record=PageOptions¦CenterHorizontal=True¦CenterVertical=True¦PrintScale=0.69¦XCorrection=1.00¦YCorrection=1.00¦PrintKind=0¦BorderSize=5000000¦LeftOffset=0¦BottomOffset=0¦Orientation=2¦PaperLength=1000¦PaperWidth=1000¦Scale=100¦PaperSource=15¦PrintQuality=600¦MediaType=1¦DitherType=10¦PaperKind=Letter¦PrintScaleMode=1
Used 2 times, as channels VS1, VS2. Parts and nets are listed once, with the designators drawn on the sheet.
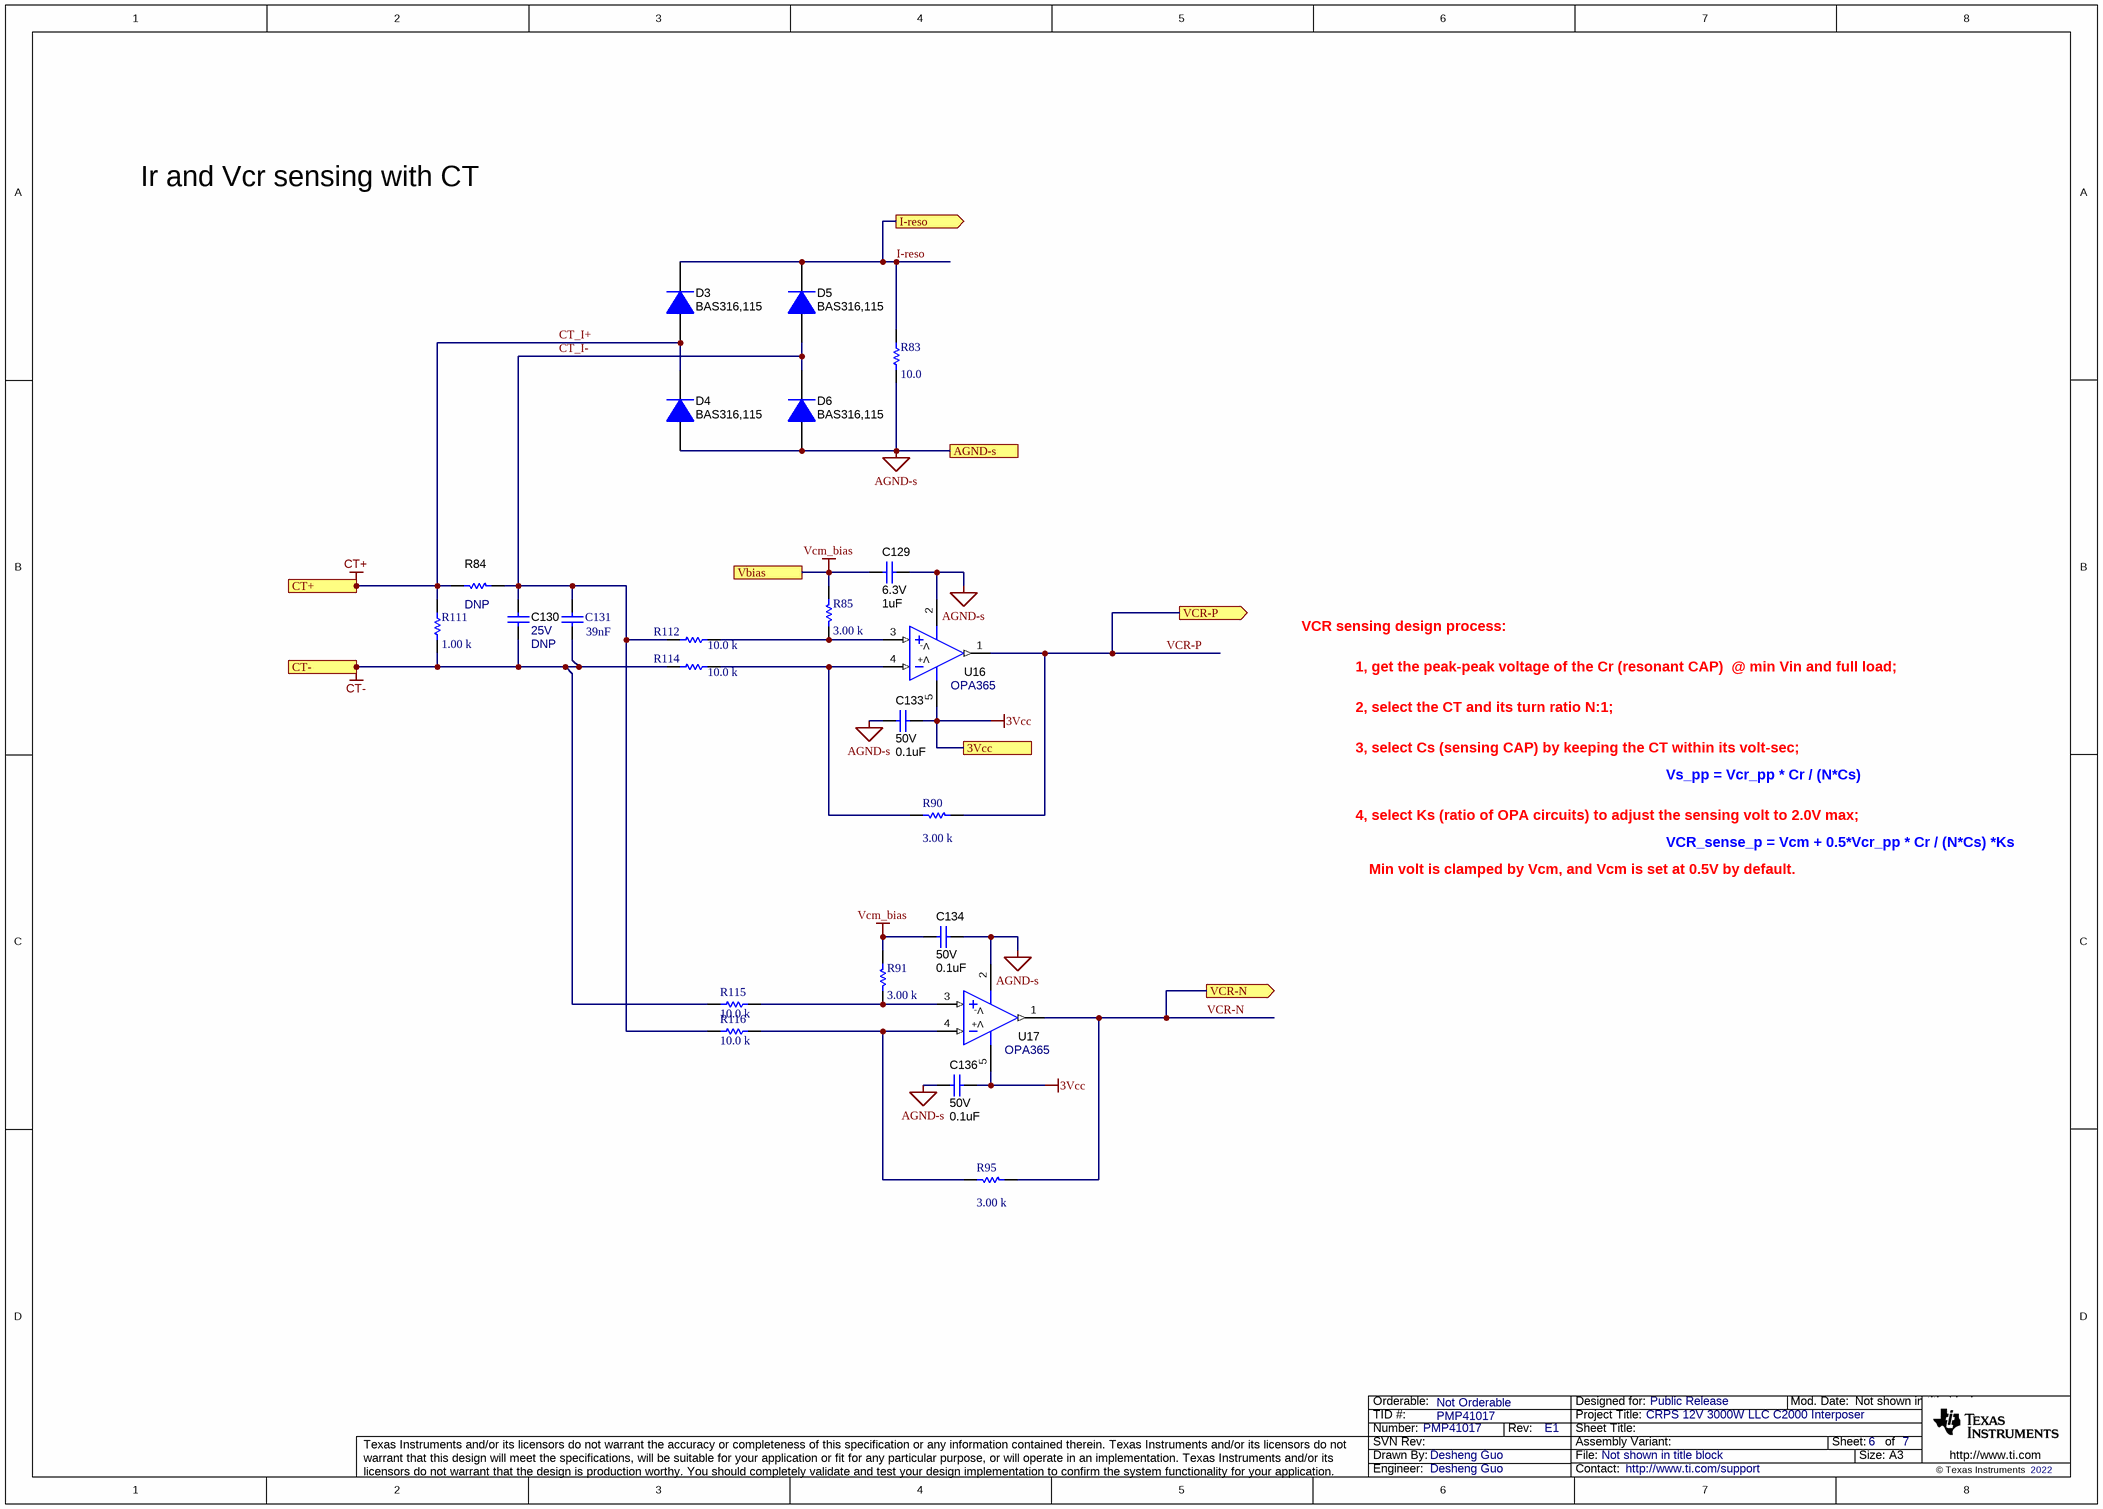
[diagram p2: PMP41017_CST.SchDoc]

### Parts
C129  VDC_V: 6.3V  ValueDisplayed: 1uF  [0402]  (hidden comment: GRM155R70J105KA12D)
C130  VDC_V: 25V  [0603]  (hidden comment: DNP)  (no BOM)
C131  value 39nF  [0402]
C133  VDC_V: 50V  ValueDisplayed: 0.1uF  [0402]  (hidden comment: C1005X7R1H104K050BE)
C134  VDC_V: 50V  ValueDisplayed: 0.1uF  [0402]  (hidden comment: C1005X7R1H104K050BE)
C136  VDC_V: 50V  ValueDisplayed: 0.1uF  [0402]  (hidden comment: C1005X7R1H104K050BE)
D3  BAS316,115  [SOD-323]
D4  BAS316,115  [SOD-323]
D5  BAS316,115  [SOD-323]
D6  BAS316,115  [SOD-323]
R83  value 10.0  [0402]
R84  ValueDisplayed: DNP  [0603]  (hidden comment: NC)  (no BOM)
R85  value 3.00 k  [0402]
R90  value 3.00 k  [0402]
R91  value 3.00 k  [0402]
R95  value 3.00 k  [0402]
R111  value 1.00 k  [0402]
R112  value 10.0 k  [0402]
R114  value 10.0 k  [0402]
R115  value 10.0 k  [0402]
R116  value 10.0 k  [0402]
U16  OPA365  [DBV0005A_N]
U17  OPA365  [DBV0005A_N]

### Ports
3Vcc, AGND-s, CT+, CT-, I-reso (out), Vbias, VCR-N (out), VCR-P (out)

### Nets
3Vcc: C133.2 C136.2 U16.5(V+) U17.5(V+) ; port 3Vcc
AGND-s: C129.1 C133.1 C134.2 C136.1 D4.2(A) D6.2(A) R83.1 U16.2(V-) U17.2(V-) ; port AGND-s
CT-: C130.1 C131.2 R111.1 R114.2 R115.2 ; port CT-
CT_I+: D3.2(A) D4.1(K) R84.2 R111.2 ; port CT+  [also labelled CT+]
Vcm_bias: C129.2 C134.1 R85.1 R91.1 ; port Vbias
CT_I-: C130.2 C131.1 D5.2(A) D6.1(K) R84.1 R112.2 R116.2  [project net CT_I-_6]
I-reso: D3.1(K) D5.1(K) R83.2 ; port I-reso
VCR-N: R95.1 U17.1(OUT) ; port VCR-N
VCR-P: R90.1 U16.1(OUT) ; port VCR-P
NetR85_2: R85.2 R112.1 U16.3(IN+)
NetR90_2: R90.2 R114.1 U16.4(IN-)
NetR91_2: R91.2 R115.1 U17.3(IN+)
NetR95_2: R95.2 R116.1 U17.4(IN-)

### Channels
VS1: designators end in _VS1; ports 3Vcc=3V3-s AGND-s=AGND-s CT+=CT1+ CT-=CT1- I-reso=I-reso Vbias=Vcm_bias VCR-N=VCR-N VCR-P=VCR-P
VS2: designators end in _VS2; ports 3Vcc=3V3-s AGND-s=AGND-s CT+=CT1+ CT-=CT1- I-reso=I-reso Vbias=Vcm_bias VCR-N=VCR-N VCR-P=VCR-P

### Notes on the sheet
- Ir and Vcr sensing with CT
- VCR sensing design process:
- 1, get the peak-peak voltage of the Cr (resonant CAP)  @ min Vin and full load;
- 2, select the CT and its turn ratio N:1;
- 3, select Cs (sensing CAP) by keeping the CT within its volt-sec;
- Vs_pp = Vcr_pp * Cr / (N*Cs)
- 4, select Ks (ratio of OPA circuits) to adjust the sensing volt to 2.0V max;
- VCR_sense_p = Vcm + 0.5*Vcr_pp * Cr / (N*Cs) *Ks
- Min volt is clamped by Vcm, and Vcm is set at 0.5V by default.

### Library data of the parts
C129 = CMP-0064947-2: CAP, CERM, 1 uF, 6.3 V,+/- 10%, X7R, 0402; Manufacturer: MuRata; TaMin_C: -55°C; Polarized: N; SizeAreaWB_mm2: 3; Value1: Unknown; U/M: EA; Value: 1uF; TaMax_C: 125°C; SizeZ_mm: 0.6; SizeX_mm: 1; SizeY_mm: 0.5; Cap_F: 1µF; AEC Category: Q200
C130 = CMP-0007039-5: CAP, CERM, 39nF, 25 V, +/- 10%, NP0, 0603; Manufacturer: TDK; PartNumber: CC0603KRX7R8BB393; TaMin_C: -55°C; Polarized: N; SizeAreaWB_mm2: 4.68; Value1: Unknown; U/M: EA; TaMax_C: 125°C; SizeZ_mm: 1; SizeX_mm: 1.6; SizeY_mm: 0.8; SizeArea_mm2: 1.28; AEC Category: Q200
C131 = Cap: CAP, CERM, 39nF, 25 V, +/- 10%, NP0, 0402
C133 C134 C136 = CMP-0064946-2: CAP, CERM, 0.1 uF, 50 V,+/- 10%, X7R, 0402; Manufacturer: TDK; TaMin_C: -55°C; Polarized: N; SizeAreaWB_mm2: 3; Value1: Unknown; U/M: EA; Value: 0.1uF; TaMax_C: 125°C; SizeZ_mm: 0.6; SizeX_mm: 1; SizeY_mm: 0.5; Cap_F: 100nF; AEC Category: Q200
D3-D6 = CMP-0029006-2: Diode, Ultrafast, 100 V, 0.25 A, SOD-323; Manufacturer: Nexperia; SizeY_mm: 1.35; Value1: 0.25A; SizeAreaWB_mm2: 8.695; SizeZ_mm: 1; Io_A: 250mA; Value2: 1.4V; SizeX_mm: 2.7; Green_REACh: Incomplete; TJmax_C: 150°C; Green_Lifecycle: Not Set; Vr_V: 100V; AEC Category: Q101; Value: 100V; SizeArea_mm2: 3.645
R83 = Res1: RES, 10.0, 1%, 0402
R84 = CMP-0022680-4: RES, 10R, 1%, 0.1 W, 0603; Manufacturer: Panasonic; Power_W: 100mW; TempCo: 100 ppm/C; Value_Code: 100; U/M: EA; Value: 10; EIA_Code: E96; Res_ohm: 1k; SizeX_mm: 1.6; SizeY_mm: 0.8; SizeZ_mm: 1; SizeArea_mm2: 1.28; VDC_V: 75V; AEC Category: Q200; Value2: 0.1W
R85 R90 R91 R95 = Res1: RES, 3.00 k, 1%, 0402
R111 = Res1: RES, 1.00 k, 1%, 0402
R112 R114-R116 = Res1: RES, 10.0 k, 1%, 0.1 W, 0402
U16 U17 = CMP-0861047-2: 50-MHz, Low-Power, Gain of 6-V/V Stable, Rail-to-Rail Output CMOS Operational Amplifier, DBV0005A (SOT-23-5); Manufacturer: Texas Instruments; AEC Category: Q200; SizeY_mm: 2.9; SizeArea_mm2: 8.12; SizeX_mm: 2.8; SizeZ_mm: 1.45; SizeAreaWB_mm2: 14.82; AEC Qualified: N; CompType: IC

## Sheet PMP41017_HSEC120.SchDoc
size A3; Date: Not shown in title block; ApprovedBy: Not shown in title block; CheckedBy: Not shown in title block; Author: Not shown in title block; CompanyName: Not shown in title block; DrawnBy: Desheng Guo; Engineer: Not shown in title block; Organization: Not shown in title block; Address1: Not shown in title block; Address2: Not shown in title block; Address3: Not shown in title block; Address4: Not shown in title block; DocumentNumber: 1; Revision: Use project parameter SCH_Rev; SheetNumber: 3; SheetTotal: 3; PageSetup: Record=PageOptions¦CenterHorizontal=True¦CenterVertical=True¦PrintScale=0.69¦XCorrection=1.00¦YCorrection=1.00¦PrintKind=0¦BorderSize=5000000¦LeftOffset=0¦BottomOffset=0¦Orientation=2¦PaperLength=1000¦PaperWidth=1000¦Scale=100¦PaperSource=15¦PrintQuality=600¦MediaType=1¦DitherType=10¦PaperKind=Letter¦PrintScaleMode=1
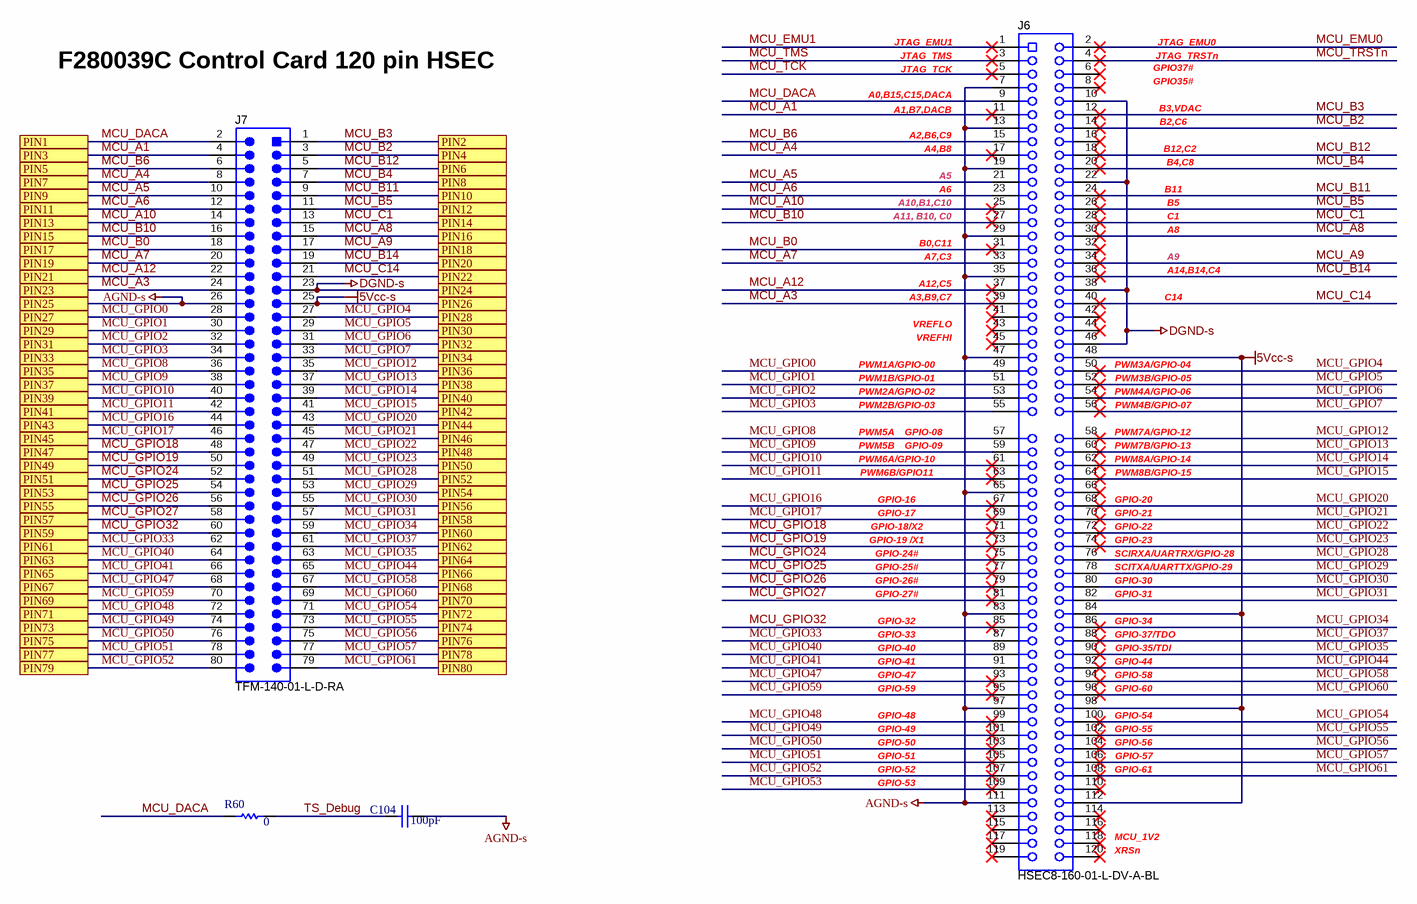
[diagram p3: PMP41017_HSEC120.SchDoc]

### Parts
C104  value 100pF  [0402]  (hidden comment: Cap)
J6  HSEC8-160-01-L-DV-A-BL  [controlCARD-120HSEC]
J7  TFM-140-01-L-D-RA  [Samtec_TFM-140-01-x-D-RA]
R60  value 0  [0402]

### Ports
PIN1, PIN2, PIN3, PIN4, PIN5, PIN6, PIN7, PIN8, PIN9, PIN10, PIN11, PIN12, PIN13, PIN14, PIN15, PIN16, PIN17, PIN18, PIN19, PIN20, PIN21, PIN22, PIN23, PIN24, PIN25, PIN26, PIN27, PIN28, PIN29, PIN30, PIN31, PIN32, PIN33, PIN34, PIN35, PIN36, PIN37, PIN38, PIN39, PIN40, PIN41, PIN42, PIN43, PIN44, PIN45, PIN46, PIN47, PIN48, PIN49, PIN50, PIN51, PIN52, PIN53, PIN54, PIN55, PIN56, PIN57, PIN58, PIN59, PIN60, PIN61, PIN62, PIN63, PIN64, PIN65, PIN66, PIN67, PIN68, PIN69, PIN70, PIN71, PIN72, PIN73, PIN74, PIN75, PIN76, PIN77, PIN78, PIN79, PIN80

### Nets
5Vcc-s: J6.48 J6.84 J6.98 J6.112 J7.25 ; port PIN26
AGND-s: C104.1 J6.7 J6.13 J6.19 J6.29 J6.35 J6.47 J6.65 J6.83 J6.97 J6.111 J7.26 ; port PIN25
DGND-s: J6.10 J6.22 J6.38 J6.46 J7.23 ; port PIN24
MCU_A1: J6.11 J7.4 ; port PIN3
MCU_A3: J6.39 J7.24 ; port PIN23
MCU_A4: J6.17 J7.8 ; port PIN7
MCU_A5: J6.21 J7.10 ; port PIN9
MCU_A6: J6.23 J7.12 ; port PIN11
MCU_A7: J6.33 J7.20 ; port PIN19
MCU_A8: J6.30 J7.15 ; port PIN16
MCU_A9: J6.34 J7.17 ; port PIN18
MCU_A10: J6.25 J7.14 ; port PIN13
MCU_A12: J6.37 J7.22 ; port PIN21
MCU_B0: J6.31 J7.18 ; port PIN17
MCU_B2: J6.14 J7.3 ; port PIN4
MCU_B3: J6.12 J7.1 ; port PIN2
MCU_B4: J6.20 J7.7 ; port PIN8
MCU_B5: J6.26 J7.11 ; port PIN12
MCU_B6: J6.15 J7.6 ; port PIN5
MCU_B10: J6.27 J7.16 ; port PIN15
MCU_B11: J6.24 J7.9 ; port PIN10
MCU_B12: J6.18 J7.5 ; port PIN6
MCU_B14: J6.36 J7.19 ; port PIN20
MCU_C1: J6.28 J7.13 ; port PIN14
MCU_C14: J6.40 J7.21 ; port PIN22
MCU_DACA: J6.9 J7.2 R60.2 ; port PIN1
MCU_EMU0: J6.2  [project net MCU_EMU0_3]
MCU_EMU1: J6.1  [project net MCU_EMU1_3]
MCU_GPIO0: J6.49 J7.28 ; port PIN27
MCU_GPIO1: J6.51 J7.30 ; port PIN29
MCU_GPIO2: J6.53 J7.32 ; port PIN31
MCU_GPIO3: J6.55 J7.34 ; port PIN33
MCU_GPIO4: J6.50 J7.27 ; port PIN28
MCU_GPIO5: J6.52 J7.29 ; port PIN30
MCU_GPIO6: J6.54 J7.31 ; port PIN32
MCU_GPIO7: J6.56 J7.33 ; port PIN34
MCU_GPIO8: J6.57 J7.36 ; port PIN35
MCU_GPIO9: J6.59 J7.38 ; port PIN37
MCU_GPIO10: J6.61 J7.40 ; port PIN39
MCU_GPIO11: J6.63 J7.42 ; port PIN41
MCU_GPIO12: J6.58 J7.35 ; port PIN36
MCU_GPIO13: J6.60 J7.37 ; port PIN38
MCU_GPIO14: J6.62 J7.39 ; port PIN40
MCU_GPIO15: J6.64 J7.41 ; port PIN42
MCU_GPIO16: J6.67 J7.44 ; port PIN43
MCU_GPIO17: J6.69 J7.46 ; port PIN45
MCU_GPIO18: J6.71 J7.48 ; port PIN47
MCU_GPIO19: J6.73 J7.50 ; port PIN49
MCU_GPIO20: J6.68 J7.43 ; port PIN44
MCU_GPIO21: J6.70 J7.45 ; port PIN46
MCU_GPIO22: J6.72 J7.47 ; port PIN48
MCU_GPIO23: J6.74 J7.49 ; port PIN50
MCU_GPIO24: J6.75 J7.52 ; port PIN51
MCU_GPIO25: J6.77 J7.54 ; port PIN53
MCU_GPIO26: J6.79 J7.56 ; port PIN55
MCU_GPIO27: J6.81 J7.58 ; port PIN57
MCU_GPIO28: J6.76 J7.51 ; port PIN52
MCU_GPIO29: J6.78 J7.53 ; port PIN54
MCU_GPIO30: J6.80 J7.55 ; port PIN56
MCU_GPIO31: J6.82 J7.57 ; port PIN58
MCU_GPIO32: J6.85 J7.60 ; port PIN59
MCU_GPIO33: J6.87 J7.62 ; port PIN61
MCU_GPIO34: J6.86 J7.59 ; port PIN60
MCU_GPIO35: J6.90 J7.63 ; port PIN64
MCU_GPIO37: J6.88 J7.61 ; port PIN62
MCU_GPIO40: J6.89 J7.64 ; port PIN63
MCU_GPIO41: J6.91 J7.66 ; port PIN65
MCU_GPIO44: J6.92 J7.65 ; port PIN66
MCU_GPIO47: J6.93 J7.68 ; port PIN67
MCU_GPIO48: J6.99 J7.72 ; port PIN71
MCU_GPIO49: J6.101 J7.74 ; port PIN73
MCU_GPIO50: J6.103 J7.76 ; port PIN75
MCU_GPIO51: J6.105 J7.78 ; port PIN77
MCU_GPIO52: J6.107 J7.80 ; port PIN79
MCU_GPIO53: J6.109  [project net MCU_GPIO53_3]
MCU_GPIO54: J6.100 J7.71 ; port PIN72
MCU_GPIO55: J6.102 J7.73 ; port PIN74
MCU_GPIO56: J6.104 J7.75 ; port PIN76
MCU_GPIO57: J6.106 J7.77 ; port PIN78
MCU_GPIO58: J6.94 J7.67 ; port PIN68
MCU_GPIO59: J6.95 J7.70 ; port PIN69
MCU_GPIO60: J6.96 J7.69 ; port PIN70
MCU_GPIO61: J6.108 J7.79 ; port PIN80
MCU_TCK: J6.5  [project net MCU_TCK_3]
MCU_TMS: J6.3  [project net MCU_TMS_3]
MCU_TRSTn: J6.4  [project net MCU_TRSTn_3]
TS_Debug: C104.2 R60.1  [project net TS_Debug_3]

Not connected (* = marked no-connect by the designer): J6 6* 8* 16* 32* 41* 42* 43* 44* 45* 66* 110* 113* 114* 115* 116* 117* 118* 119* 120*

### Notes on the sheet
- JTAG_EMU1
- JTAG_EMU0
- F280039C Control Card 120 pin HSEC
- A0,B15,C15,DACA
- A1,B7,DACB
- JTAG_TCK
- JTAG_TMS
- GPIO37#
- GPIO35#
- B3,VDAC
- JTAG_TRSTn
- A2,B6,C9
- A4,B8
- A5
- B2,C6
- B12,C2
- B4,C8
- A11, B10, C0
- A10,B1,C10
- B0,C11
- A6
- B11
- C1
- A8
- B5
- A3,B9,C7
- A12,C5
- A7,C3
- A9
- C14
- A14,B14,C4
- PWM1A/GPIO-00
- PWM1B/GPIO-01
- VREFLO
- VREFHI
- (near J6) PWM3A/GPIO-04
- (near J6) PWM3B/GPIO-05
- PWM5A
- PWM5B
- PWM2A/GPIO-02
- PWM2B/GPIO-03
- GPIO-08
- GPIO-09
- (near J6) PWM7B/GPIO-13
- (near J6) PWM7A/GPIO-12
- (near J6) PWM4A/GPIO-06
- (near J6) PWM4B/GPIO-07
- PWM6A/GPIO-10
- PWM6B/GPIO11
- GPIO-16
- GPIO-17
- (near J6) GPIO-21
- (near J6) GPIO-20
- (near J6) PWM8A/GPIO-14
- (near J6) PWM8B/GPIO-15
- GPIO-24#
- GPIO-25#
- GPIO-26#
- GPIO-19 /X1
- GPIO-18/X2
- (near J6) GPIO-23
- (near J6) GPIO-22
- (near J6) GPIO-30
- (near J6) SCITXA/UARTTX/GPIO-29
- (near J6) SCIRXA/UARTRX/GPIO-28
- GPIO-27#
- GPIO-32
- GPIO-33
- GPIO-40
- (near J6) GPIO-31
- (near J6) GPIO-34
- (near J6) GPIO-35/TDI
- (near J6) GPIO-37/TDO
- GPIO-48
- GPIO-41
- GPIO-47
- GPIO-59
- (near J6) GPIO-54
- (near J6) GPIO-44
- (near J6) GPIO-58
- (near J6) GPIO-60
- GPIO-49
- GPIO-50
- GPIO-51
- GPIO-52
- GPIO-53
- (near J6) GPIO-61
- (near J6) GPIO-56
- (near J6) GPIO-55
- (near J6) GPIO-57
- (near J6) XRSn
- (near J6) MCU_1V2

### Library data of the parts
C104 = Cap: as C74 on sheet PMP41017_C2000Interposer
J6 = CMP-0003814-2: C2000 controlCARD-120HSEC connector, SMT; Manufacturer: Samtec; Note: The pin numbering does not match Samtec datasheet
J7 = CMP-0081930-1: Header(shrouded), 1.27mm, 40x2, Gold with Tin tail, R/A, TH; Manufacturer: Samtec; Pitch_mm: 1.27; Gender: Male; Cert_UL: Y; Voltage_V: 250V; Current_A: 3.2A; Row_Count: 2
R60 = Res1: as R3 on sheet PMP41017_C2000Interposer

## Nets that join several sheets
3V3-s: PMP41017_C2000Interposer (13 pins), VS1 (C133_VS1.2 C136_VS1.2 U16_VS1.5 U17_VS1.5), VS2 (C133_VS2.2 C136_VS2.2 U16_VS2.5 U17_VS2.5)
5Vcc-s: PMP41017_C2000Interposer (9 pins), PMP41017_HSEC120 (5 pins)
AGND-s: PMP41017_C2000Interposer (16 pins), VS1 (9 pins), VS2 (9 pins), PMP41017_HSEC120 (12 pins)
CT1+: PMP41017_C2000Interposer (J5.20 J5.22), VS1 (D3_VS1.2 D4_VS1.1 R84_VS1.2 R111_VS1.2), VS2 (D3_VS2.2 D4_VS2.1 R84_VS2.2 R111_VS2.2)
CT1-: PMP41017_C2000Interposer (J5.19 J5.21), VS1 (5 pins), VS2 (5 pins)
DGND-s: PMP41017_C2000Interposer (34 pins), PMP41017_HSEC120 (5 pins)
Vcm_bias: PMP41017_C2000Interposer (R22.2 R64.2), VS1 (C129_VS1.2 C134_VS1.1 R85_VS1.1 R91_VS1.1), VS2 (C129_VS2.2 C134_VS2.1 R85_VS2.1 R91_VS2.1)
I-reso: PMP41017_C2000Interposer (R12.2), VS2 (D3_VS2.1 D5_VS2.1 R83_VS2.2)
I-reso: PMP41017_C2000Interposer (R11.2), VS1 (D3_VS1.1 D5_VS1.1 R83_VS1.2)
VCR-N: PMP41017_C2000Interposer (R16.2), VS1 (R95_VS1.1 U17_VS1.1)
VCR-N: PMP41017_C2000Interposer (R18.2), VS2 (R95_VS2.1 U17_VS2.1)
VCR-P: PMP41017_C2000Interposer (R15.2), VS1 (R90_VS1.1 U16_VS1.1)
VCR-P: PMP41017_C2000Interposer (R17.2), VS2 (R90_VS2.1 U16_VS2.1)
